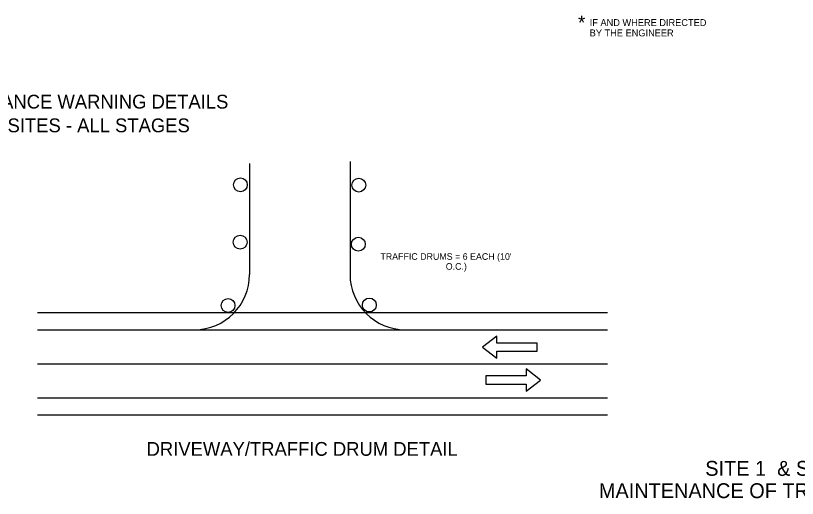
# Model space of a CAD drawing. Extents: x -160 to 6143532, y -375 to 762199.
# Drawn here: x -92.5 to -21.5, y 3.9 to 47.6 of the extents above; entities that cross this region are included whole.
import ezdxf

# ---------------------------------------------------------------- set-up
doc = ezdxf.new("R2010")
doc.units = 0
for name, color, linetype in [('R_Annotation', 7, 'Continuous'), ('R_Centerline', 7, 'Continuous'), ('R_Drive', 7, 'Continuous'), ('R_MOT', 7, 'Continuous'), ('R_Proposed Road_Lane', 7, 'Continuous'), ('R_Proposed Road_Shoulder', 7, 'Continuous'), ('R_Striping', 7, 'Continuous')]:
    doc.layers.add(name, color=color, linetype=linetype)

msp = doc.modelspace()

# ---------------------------------------------------------------- linework, layer by layer
at = {"layer": 'R_Centerline'}
msp.add_line((-90.485, 16.056), (-38.782, 16.056), dxfattribs=at)
at = {"layer": 'R_Drive'}
for p, q in [((-71.244, 34.215), (-71.244, 24.147)), ((-62.126, 34.386), (-62.126, 24.147))]:
    msp.add_line(p, q, dxfattribs=at)
for centre, start, end in [((-76.244, 24.147), 270, 0), ((-57.126, 24.147), 180, 270)]:
    msp.add_arc(centre, 5, start, end, dxfattribs=at)
at = {"layer": 'R_MOT'}
for centre in [(-72.074, 32.274), (-61.333, 32.251), (-72.095, 27.077), (-61.375, 26.894), (-60.376, 21.383), (-73.194, 21.338)]:
    msp.add_circle(centre, 0.625, dxfattribs=at)
at = {"layer": 'R_Proposed Road_Lane'}
for p, q in [((-90.485, 19.147), (-38.782, 19.147)), ((-90.485, 12.965), (-38.782, 12.965))]:
    msp.add_line(p, q, dxfattribs=at)
at = {"layer": 'R_Proposed Road_Shoulder'}
for p, q in [((-90.485, 20.693), (-38.782, 20.693)), ((-90.485, 11.419), (-38.782, 11.419))]:
    msp.add_line(p, q, dxfattribs=at)
at = {"layer": 'R_Striping'}
for points in [[(-48.814, 18.561), (-50.112, 17.561), (-48.814, 16.561), (-48.814, 17.186), (-45.136, 17.186), (-45.136, 17.936), (-48.814, 17.936)], [(-46.141, 13.582), (-44.843, 14.582), (-46.141, 15.582), (-46.141, 14.957), (-49.819, 14.957), (-49.819, 14.207), (-46.141, 14.207)]]:
    msp.add_lwpolyline(points, close=True, dxfattribs=at)

# ---------------------------------------------------------------- texts
at = {"layer": 'R_Annotation'}
for s, height, p in [('*', 1.25, (-41.439, 46.365)), ('IF AND WHERE DIRECTED ', 0.625, (-40.38, 46.674)), ('BY THE ENGINEER', 0.625, (-40.38, 45.737)), ('ADVANCE WARNING DETAILS ', 1.25, (-97.22, 39.193)), ('ALL SITES - ALL STAGES', 1.25, (-96.64, 37.043)), ("TRAFFIC DRUMS = 6 EACH (10' ", 0.6, (-59.372, 25.479)), ('O.C.)', 0.6, (-53.443, 24.579)), ('DRIVEWAY/TRAFFIC DRUM DETAIL', 1.25, (-80.585, 7.712))]:
    msp.add_text(s, height=height, dxfattribs=at).set_placement(p)
at = {"layer": 'R_Striping'}
for s, p in [('SITE 1  & SITE 2', (-29.897, 5.9)), ('MAINTENANCE OF TRAFFIC DETAILS', (-39.549, 3.875))]:
    msp.add_text(s, height=1.35, dxfattribs=at).set_placement(p)

doc.saveas('drawing.dxf')
